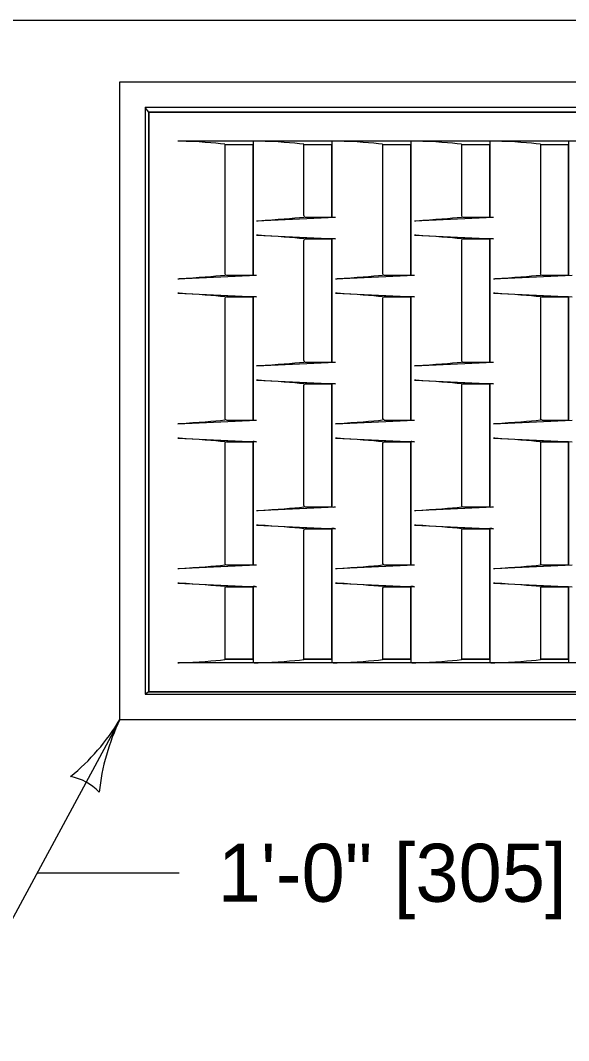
# Model space of a CAD drawing. Extents: x 49991.4 to 50021, y 49987.6 to 50011.4.
# Drawn here: x 50001.882 to 50002.449, y 49997.234 to 49998.29 of the extents above; entities that cross this region are included whole.
import ezdxf

# ---------------------------------------------------------------- set-up
doc = ezdxf.new("R2010")
doc.units = 0
for name, color, linetype in [('Level 1', 7, 'Continuous'), ('Level 18', 7, 'Continuous'), ('Level 2', 7, 'Continuous'), ('Level 3', 7, 'Continuous')]:
    doc.layers.add(name, color=color, linetype=linetype)

msp = doc.modelspace()

# ---------------------------------------------------------------- linework, layer by layer
at = {"layer": 'Level 1'}
for p, q in [((50003.5566, 49998.2898), (50001.1926, 49998.2898)), ((50001.9846, 49997.5662), (50001.9846, 49998.2261)), ((50001.9846, 49998.2261), (50002.7646, 49998.2261)), ((50002.0108, 49998.1998), (50002.0108, 49997.5925)), ((50002.0146, 49998.195), (50002.0108, 49998.1998)), ((50002.7383, 49998.1998), (50002.0108, 49998.1998)), ((50002.7346, 49998.195), (50002.0146, 49998.195)), ((50002.6946, 49998.165), (50002.0446, 49998.165)), ((50002.1224, 49998.1647), (50002.1224, 49998.0262)), ((50002.2039, 49998.1647), (50002.2039, 49998.0862)), ((50002.2855, 49998.1647), (50002.2855, 49998.0262)), ((50002.367, 49998.1647), (50002.367, 49998.0862)), ((50002.4486, 49998.1647), (50002.4486, 49998.0262)), ((50002.0932, 49998.1617), (50002.0932, 49998.0278)), ((50002.1224, 49998.1612), (50002.0932, 49998.1612)), ((50002.1747, 49998.1617), (50002.1747, 49998.1612)), ((50002.2039, 49998.1612), (50002.1747, 49998.1612)), ((50002.1747, 49998.1612), (50002.1747, 49998.0878)), ((50002.2563, 49998.1617), (50002.2563, 49998.1612)), ((50002.2855, 49998.1612), (50002.2563, 49998.1612)), ((50002.2563, 49998.1612), (50002.2563, 49998.0278)), ((50002.3378, 49998.1617), (50002.3378, 49998.1612)), ((50002.367, 49998.1612), (50002.3378, 49998.1612)), ((50002.3378, 49998.1612), (50002.3378, 49998.0878)), ((50002.4194, 49998.1617), (50002.4194, 49998.1612)), ((50002.4486, 49998.1612), (50002.4194, 49998.1612)), ((50002.4194, 49998.1612), (50002.4194, 49998.0278)), ((50002.1261, 49998.0825), (50002.2077, 49998.0862)), ((50002.1763, 49998.0862), (50002.2039, 49998.0862)), ((50002.2892, 49998.0825), (50002.3708, 49998.0862)), ((50002.3394, 49998.0862), (50002.367, 49998.0862)), ((50002.1261, 49998.0675), (50002.2077, 49998.0637)), ((50002.2892, 49998.0675), (50002.3708, 49998.0637)), ((50002.1747, 49998.0622), (50002.1747, 49997.9378)), ((50002.1763, 49998.0637), (50002.2039, 49998.0637)), ((50002.2039, 49998.0638), (50002.2039, 49997.9362)), ((50002.3378, 49998.0622), (50002.3378, 49997.9378)), ((50002.3394, 49998.0637), (50002.367, 49998.0637)), ((50002.367, 49998.0638), (50002.367, 49997.9362)), ((50002.0446, 49998.0225), (50002.1261, 49998.0263)), ((50002.0948, 49998.0263), (50002.1224, 49998.0263)), ((50002.2077, 49998.0225), (50002.2892, 49998.0263)), ((50002.2579, 49998.0263), (50002.2855, 49998.0263)), ((50002.3708, 49998.0225), (50002.4523, 49998.0263)), ((50002.4209, 49998.0263), (50002.4486, 49998.0263)), ((50002.0446, 49998.0075), (50002.1261, 49998.0038)), ((50002.0948, 49998.0038), (50002.1224, 49998.0038)), ((50002.1224, 49998.0038), (50002.1224, 49997.8763)), ((50002.2077, 49998.0075), (50002.2892, 49998.0038)), ((50002.2579, 49998.0038), (50002.2855, 49998.0038)), ((50002.2855, 49998.0038), (50002.2855, 49997.8763)), ((50002.3708, 49998.0075), (50002.4523, 49998.0038)), ((50002.4209, 49998.0038), (50002.4486, 49998.0038)), ((50002.4486, 49998.0038), (50002.4486, 49997.8763)), ((50002.0932, 49998.0022), (50002.0932, 49997.8779)), ((50002.2563, 49998.0022), (50002.2563, 49997.8779)), ((50002.4194, 49998.0022), (50002.4194, 49997.8779)), ((50002.1261, 49997.9325), (50002.2077, 49997.9363)), ((50002.1763, 49997.9363), (50002.2039, 49997.9363)), ((50002.2892, 49997.9325), (50002.3708, 49997.9363)), ((50002.3394, 49997.9363), (50002.367, 49997.9363)), ((50002.1261, 49997.9175), (50002.2077, 49997.9138)), ((50002.1747, 49997.9122), (50002.1747, 49997.7879)), ((50002.1763, 49997.9138), (50002.2039, 49997.9138)), ((50002.2039, 49997.9138), (50002.2039, 49997.7863)), ((50002.2892, 49997.9175), (50002.3708, 49997.9138)), ((50002.3378, 49997.9122), (50002.3378, 49997.7879)), ((50002.3394, 49997.9138), (50002.367, 49997.9138)), ((50002.367, 49997.9138), (50002.367, 49997.7863)), ((50002.0446, 49997.8725), (50002.1261, 49997.8763)), ((50002.0948, 49997.8763), (50002.1224, 49997.8763)), ((50002.2077, 49997.8725), (50002.2892, 49997.8763)), ((50002.2579, 49997.8763), (50002.2855, 49997.8763)), ((50002.3708, 49997.8725), (50002.4523, 49997.8763)), ((50002.4209, 49997.8763), (50002.4486, 49997.8763)), ((50002.0446, 49997.8575), (50002.1261, 49997.8538)), ((50002.2077, 49997.8575), (50002.2892, 49997.8538)), ((50002.3708, 49997.8575), (50002.4523, 49997.8538)), ((50002.0932, 49997.8522), (50002.0932, 49997.7279)), ((50002.0948, 49997.8538), (50002.1224, 49997.8538)), ((50002.1224, 49997.8538), (50002.1224, 49997.7263)), ((50002.2563, 49997.8522), (50002.2563, 49997.7279)), ((50002.2579, 49997.8538), (50002.2855, 49997.8538)), ((50002.2855, 49997.8538), (50002.2855, 49997.7263)), ((50002.4194, 49997.8522), (50002.4194, 49997.7279)), ((50002.4209, 49997.8538), (50002.4486, 49997.8538)), ((50002.4486, 49997.8538), (50002.4486, 49997.7263)), ((50002.1261, 49997.7826), (50002.2077, 49997.7863)), ((50002.1763, 49997.7863), (50002.2039, 49997.7863)), ((50002.2892, 49997.7826), (50002.3708, 49997.7863)), ((50002.3394, 49997.7863), (50002.367, 49997.7863)), ((50002.1261, 49997.7676), (50002.2077, 49997.7638)), ((50002.1747, 49997.7623), (50002.1747, 49997.6289)), ((50002.1763, 49997.7638), (50002.2039, 49997.7638)), ((50002.2039, 49997.7639), (50002.2039, 49997.6254)), ((50002.2892, 49997.7676), (50002.3708, 49997.7638)), ((50002.3378, 49997.7623), (50002.3378, 49997.6289)), ((50002.3394, 49997.7638), (50002.367, 49997.7638)), ((50002.367, 49997.7639), (50002.367, 49997.6254)), ((50002.0446, 49997.7226), (50002.1261, 49997.7263)), ((50002.0948, 49997.7263), (50002.1224, 49997.7263)), ((50002.2077, 49997.7226), (50002.2892, 49997.7263)), ((50002.2579, 49997.7263), (50002.2855, 49997.7263)), ((50002.3708, 49997.7226), (50002.4523, 49997.7263)), ((50002.4209, 49997.7263), (50002.4486, 49997.7263)), ((50002.0446, 49997.7076), (50002.1261, 49997.7038)), ((50002.0932, 49997.7023), (50002.0932, 49997.6284)), ((50002.0948, 49997.7038), (50002.1224, 49997.7038)), ((50002.1224, 49997.7039), (50002.1224, 49997.6254)), ((50002.2077, 49997.7076), (50002.2892, 49997.7038)), ((50002.2563, 49997.7023), (50002.2563, 49997.6289)), ((50002.2579, 49997.7038), (50002.2855, 49997.7038)), ((50002.2855, 49997.7039), (50002.2855, 49997.6254)), ((50002.3708, 49997.7076), (50002.4523, 49997.7038)), ((50002.4194, 49997.7023), (50002.4194, 49997.6289)), ((50002.4209, 49997.7038), (50002.4486, 49997.7038)), ((50002.4486, 49997.7039), (50002.4486, 49997.6254)), ((50002.6946, 49997.6251), (50002.0446, 49997.6251)), ((50002.1224, 49997.6289), (50002.0932, 49997.6289)), ((50002.2039, 49997.6289), (50002.1747, 49997.6289)), ((50002.1747, 49997.6289), (50002.1747, 49997.6284)), ((50002.2855, 49997.6289), (50002.2563, 49997.6289)), ((50002.2563, 49997.6289), (50002.2563, 49997.6284)), ((50002.367, 49997.6289), (50002.3378, 49997.6289)), ((50002.3378, 49997.6289), (50002.3378, 49997.6284)), ((50002.4486, 49997.6289), (50002.4194, 49997.6289)), ((50002.4194, 49997.6289), (50002.4194, 49997.6284)), ((50002.0146, 49997.5951), (50002.0108, 49997.5925)), ((50002.0108, 49997.5925), (50002.7383, 49997.5925)), ((50002.0146, 49997.5951), (50002.7346, 49997.5951)), ((50002.7646, 49997.5662), (50001.9846, 49997.5662))]:
    msp.add_line(p, q, dxfattribs=at)
msp.add_lwpolyline([(50002.0146, 49998.195), (50002.7344, 49998.195), (50002.7344, 49997.5951), (50002.0146, 49997.5951)], close=True, dxfattribs=at)
for points in [[(50002.0932, 49998.1612), (50002.0932, 49998.0278)], [(50002.0948, 49998.0263), (50002.1224, 49998.0263), (50002.1224, 49998.1612), (50002.0932, 49998.1612)], [(50002.2039, 49998.0862), (50002.2039, 49998.1612), (50002.1747, 49998.1612), (50002.1747, 49998.0878)], [(50002.2855, 49998.0263), (50002.2855, 49998.1612), (50002.2563, 49998.1612), (50002.2563, 49998.0278)], [(50002.367, 49998.0862), (50002.367, 49998.1612), (50002.3378, 49998.1612), (50002.3378, 49998.0878)], [(50002.4486, 49998.0263), (50002.4486, 49998.1612), (50002.4194, 49998.1612), (50002.4194, 49998.0278)], [(50002.1763, 49998.0862), (50002.2039, 49998.0862)], [(50002.3394, 49998.0862), (50002.367, 49998.0862)], [(50002.1747, 49998.0622), (50002.1747, 49997.9378)], [(50002.2039, 49997.9363), (50002.2039, 49998.0637), (50002.1763, 49998.0637)], [(50002.2579, 49998.0263), (50002.2855, 49998.0263)], [(50002.4209, 49998.0263), (50002.4486, 49998.0263)], [(50002.1224, 49997.8763), (50002.1224, 49998.0038), (50002.0948, 49998.0038)], [(50002.2855, 49997.8763), (50002.2855, 49998.0038), (50002.2579, 49998.0038)], [(50002.4486, 49997.8763), (50002.4486, 49998.0038), (50002.4209, 49998.0038)], [(50002.0932, 49998.0022), (50002.0932, 49997.8779)], [(50002.2563, 49998.0022), (50002.2563, 49997.8779)], [(50002.4194, 49998.0022), (50002.4194, 49997.8779)], [(50002.1763, 49997.9363), (50002.2039, 49997.9363)], [(50002.1747, 49997.9122), (50002.1747, 49997.7879)], [(50002.2039, 49997.7863), (50002.2039, 49997.9138), (50002.1763, 49997.9138)], [(50002.0948, 49997.8763), (50002.1224, 49997.8763)], [(50002.2579, 49997.8763), (50002.2855, 49997.8763)], [(50002.4209, 49997.8763), (50002.4486, 49997.8763)], [(50002.0932, 49997.8522), (50002.0932, 49997.7279)], [(50002.1224, 49997.7263), (50002.1224, 49997.8538), (50002.0948, 49997.8538)], [(50002.2563, 49997.8522), (50002.2563, 49997.7279)], [(50002.2855, 49997.7263), (50002.2855, 49997.8538), (50002.2579, 49997.8538)], [(50002.1763, 49997.7863), (50002.2039, 49997.7863)], [(50002.1747, 49997.7623), (50002.1747, 49997.6289), (50002.2039, 49997.6289)], [(50002.2039, 49997.6289), (50002.2039, 49997.7638), (50002.1763, 49997.7638)], [(50002.3378, 49997.7623), (50002.3378, 49997.6289), (50002.367, 49997.6289)], [(50002.367, 49997.6289), (50002.367, 49997.7638), (50002.3394, 49997.7638)], [(50002.0948, 49997.7263), (50002.1224, 49997.7263)], [(50002.2579, 49997.7263), (50002.2855, 49997.7263)], [(50002.2563, 49997.7023), (50002.2563, 49997.6289), (50002.2855, 49997.6289)], [(50002.2855, 49997.6289), (50002.2855, 49997.7038), (50002.2579, 49997.7038)]]:
    msp.add_lwpolyline(points, dxfattribs=at)
for centre, radius, start, end in [((50002.3746, 49998.2898), 1.2045, 180, 0), ((50002.3746, 49998.2898), 1.182, 180, 0), ((50002.1763, 49998.0878), 0.00156, 180, 270), ((50002.1763, 49998.0878), 0.00156, 180, 270), ((50002.3394, 49998.0878), 0.00156, 180, 270), ((50002.3394, 49998.0878), 0.00156, 180, 270), ((50002.1763, 49998.0622), 0.00156, 90, 180), ((50002.1763, 49998.0622), 0.00156, 90, 180), ((50002.3394, 49998.0622), 0.00156, 90, 180), ((50002.0948, 49998.0278), 0.00156, 180, 270), ((50002.0948, 49998.0278), 0.00156, 180, 270), ((50002.2579, 49998.0278), 0.00156, 180, 270), ((50002.2579, 49998.0278), 0.00156, 180, 270), ((50002.4209, 49998.0278), 0.00156, 180, 270), ((50002.4209, 49998.0278), 0.00156, 180, 270), ((50002.0948, 49998.0022), 0.00156, 90, 180), ((50002.0948, 49998.0022), 0.00156, 90, 180), ((50002.2579, 49998.0022), 0.00156, 90, 180), ((50002.2579, 49998.0022), 0.00156, 90, 180), ((50002.4209, 49998.0022), 0.00156, 90, 180), ((50002.4209, 49998.0022), 0.00156, 90, 180), ((50002.1763, 49997.9378), 0.00156, 180, 270), ((50002.1763, 49997.9378), 0.00156, 180, 270), ((50002.3394, 49997.9378), 0.00156, 180, 270), ((50002.1763, 49997.9122), 0.00156, 90, 180), ((50002.1763, 49997.9122), 0.00156, 90, 180), ((50002.3394, 49997.9122), 0.00156, 90, 180), ((50002.0948, 49997.8779), 0.00156, 180, 270), ((50002.0948, 49997.8779), 0.00156, 180, 270), ((50002.2579, 49997.8779), 0.00156, 180, 270), ((50002.2579, 49997.8779), 0.00156, 180, 270), ((50002.4209, 49997.8779), 0.00156, 180, 270), ((50002.4209, 49997.8779), 0.00156, 180, 270), ((50002.0948, 49997.8522), 0.00156, 90, 180), ((50002.0948, 49997.8522), 0.00156, 90, 180), ((50002.2579, 49997.8522), 0.00156, 90, 180), ((50002.2579, 49997.8522), 0.00156, 90, 180), ((50002.4209, 49997.8522), 0.00156, 90, 180), ((50002.1763, 49997.7879), 0.00156, 180, 270), ((50002.1763, 49997.7879), 0.00156, 180, 270), ((50002.3394, 49997.7879), 0.00156, 180, 270), ((50002.1763, 49997.7623), 0.00156, 90, 180), ((50002.1763, 49997.7623), 0.00156, 90, 180), ((50002.3394, 49997.7623), 0.00156, 90, 180), ((50002.3394, 49997.7623), 0.00156, 90, 180), ((50002.0948, 49997.7279), 0.00156, 180, 270), ((50002.0948, 49997.7279), 0.00156, 180, 270), ((50002.2579, 49997.7279), 0.00156, 180, 270), ((50002.2579, 49997.7279), 0.00156, 180, 270), ((50002.4209, 49997.7279), 0.00156, 180, 270), ((50002.0948, 49997.7023), 0.00156, 90, 180), ((50002.2579, 49997.7023), 0.00156, 90, 180), ((50002.2579, 49997.7023), 0.00156, 90, 180), ((50002.4209, 49997.7023), 0.00156, 90, 180)]:
    msp.add_arc(centre, radius, start, end, dxfattribs=at)
for centre, major_axis, ratio, start_param, end_param in [((50002.0025, 49998.1576), (0.105, 0), 0.076923, 0.527586, 1.142), ((50002.1261, 49998.1647), (0.00375, 0), 0.076923, 1.570796, 3.141593), ((50002.1261, 49998.1647), (0.00375, 0), 0.076923, 1.142, 1.570796), ((50002.084, 49998.1576), (0.105, 0), 0.076923, 0.527586, 1.142), ((50002.2077, 49998.1647), (0.00375, 0), 0.076923, 1.570796, 3.141593), ((50002.2077, 49998.1647), (0.00375, 0), 0.076923, 1.142, 1.570796), ((50002.1656, 49998.1576), (0.105, 0), 0.076923, 0.527586, 1.142), ((50002.2892, 49998.1647), (0.00375, 0), 0.076923, 1.570796, 3.141593), ((50002.2892, 49998.1647), (0.00375, 0), 0.076923, 1.142, 1.570796), ((50002.2471, 49998.1576), (0.105, 0), 0.076923, 0.527586, 1.142), ((50002.3708, 49998.1647), (0.00375, 0), 0.076923, 1.570796, 3.141593), ((50002.3708, 49998.1647), (0.00375, 0), 0.076923, 1.142, 1.570796), ((50002.3287, 49998.1576), (0.105, 0), 0.076923, 0.527586, 1.142), ((50002.084, 49998.084), (-0.105, -0.0048), 0.035758, 1.997966, 2.612379), ((50002.2077, 49998.0864), (-0.00375, -0.00017), 0.035758, 6.281558, 7.852354), ((50002.2892, 49998.0826), (-0.00375, -0.00017), 0.035758, 1.569169, 1.997966), ((50002.2471, 49998.084), (-0.105, -0.0048), 0.035758, 1.997966, 2.612379), ((50002.3708, 49998.0864), (-0.00375, -0.00017), 0.035758, 6.281558, 7.852354), ((50002.084, 49998.066), (0.105, -0.0048), 0.035758, 0.529214, 1.143627), ((50002.2892, 49998.0674), (0.00375, -0.00017), 0.035758, 1.143627, 1.572424), ((50002.2471, 49998.066), (0.105, -0.0048), 0.035758, 0.529214, 1.143627), ((50002.2077, 49998.0636), (0.00375, -0.00017), 0.035758, 1.572424, 3.14322), ((50002.3708, 49998.0636), (0.00375, -0.00017), 0.035758, 1.572424, 3.14322), ((50002.0025, 49998.024), (-0.105, -0.0048), 0.035758, 1.997966, 2.612379), ((50002.1261, 49998.0264), (-0.00375, -0.00017), 0.035758, 6.281558, 7.852354), ((50002.1656, 49998.024), (-0.105, -0.0048), 0.035758, 1.997966, 2.612379), ((50002.2892, 49998.0264), (-0.00375, -0.00017), 0.035758, 6.281558, 7.852354), ((50002.3287, 49998.024), (-0.105, -0.0048), 0.035758, 1.997966, 2.612379), ((50002.0446, 49998.0226), (-0.00375, -0.00017), 0.035758, 1.569169, 1.997966), ((50002.0446, 49998.0074), (0.00375, -0.00017), 0.035758, 1.143627, 1.572424), ((50002.0025, 49998.006), (0.105, -0.0048), 0.035758, 0.529214, 1.143627), ((50002.1261, 49998.0036), (0.00375, -0.00017), 0.035758, 1.572424, 3.14322), ((50002.1656, 49998.006), (0.105, -0.0048), 0.035758, 0.529214, 1.143627), ((50002.2892, 49998.0036), (0.00375, -0.00017), 0.035758, 1.572424, 3.14322), ((50002.3287, 49998.006), (0.105, -0.0048), 0.035758, 0.529214, 1.143627), ((50002.084, 49997.934), (-0.105, -0.0048), 0.035758, 1.997966, 2.612379), ((50002.2077, 49997.9364), (-0.00375, -0.00017), 0.035758, 6.281558, 7.852354), ((50002.2892, 49997.9327), (-0.00375, -0.00017), 0.035758, 1.569169, 1.997966), ((50002.2471, 49997.934), (-0.105, -0.0048), 0.035758, 1.997966, 2.612379), ((50002.3708, 49997.9364), (-0.00375, -0.00017), 0.035758, 6.281558, 7.852354), ((50002.084, 49997.916), (0.105, -0.0048), 0.035758, 0.529214, 1.143627), ((50002.2077, 49997.9136), (0.00375, -0.00017), 0.035758, 1.572424, 3.14322), ((50002.2892, 49997.9174), (0.00375, -0.00017), 0.035758, 1.143627, 1.572424), ((50002.2471, 49997.916), (0.105, -0.0048), 0.035758, 0.529214, 1.143627), ((50002.3708, 49997.9136), (0.00375, -0.00017), 0.035758, 1.572424, 3.14322), ((50002.0025, 49997.8741), (-0.105, -0.0048), 0.035758, 1.997966, 2.612379), ((50002.1261, 49997.8764), (-0.00375, -0.00017), 0.035758, 6.281558, 7.852354), ((50002.1656, 49997.8741), (-0.105, -0.0048), 0.035758, 1.997966, 2.612379), ((50002.2892, 49997.8764), (-0.00375, -0.00017), 0.035758, 6.281558, 7.852354), ((50002.3287, 49997.8741), (-0.105, -0.0048), 0.035758, 1.997966, 2.612379), ((50002.0025, 49997.856), (0.105, -0.0048), 0.035758, 0.529214, 1.143627), ((50002.1656, 49997.856), (0.105, -0.0048), 0.035758, 0.529214, 1.143627), ((50002.3287, 49997.856), (0.105, -0.0048), 0.035758, 0.529214, 1.143627), ((50002.1261, 49997.8537), (0.00375, -0.00017), 0.035758, 1.572424, 3.14322), ((50002.2892, 49997.8537), (0.00375, -0.00017), 0.035758, 1.572424, 3.14322), ((50002.084, 49997.7841), (-0.105, -0.0048), 0.035758, 1.997966, 2.612379), ((50002.2077, 49997.7865), (-0.00375, -0.00017), 0.035758, 6.281558, 7.852354), ((50002.2892, 49997.7827), (-0.00375, -0.00017), 0.035758, 1.569169, 1.997966), ((50002.2471, 49997.7841), (-0.105, -0.0048), 0.035758, 1.997966, 2.612379), ((50002.3708, 49997.7865), (-0.00375, -0.00017), 0.035758, 6.281558, 7.852354), ((50002.084, 49997.7661), (0.105, -0.0048), 0.035758, 0.529214, 1.143627), ((50002.2077, 49997.7637), (0.00375, -0.00017), 0.035758, 1.572424, 3.14322), ((50002.2892, 49997.7674), (0.00375, -0.00017), 0.035758, 1.143627, 1.572424), ((50002.2471, 49997.7661), (0.105, -0.0048), 0.035758, 0.529214, 1.143627), ((50002.3708, 49997.7637), (0.00375, -0.00017), 0.035758, 1.572424, 3.14322), ((50002.0025, 49997.7241), (-0.105, -0.0048), 0.035758, 1.997966, 2.612379), ((50002.1261, 49997.7265), (-0.00375, -0.00017), 0.035758, 6.281558, 7.852354), ((50002.1656, 49997.7241), (-0.105, -0.0048), 0.035758, 1.997966, 2.612379), ((50002.2892, 49997.7265), (-0.00375, -0.00017), 0.035758, 6.281558, 7.852354), ((50002.3287, 49997.7241), (-0.105, -0.0048), 0.035758, 1.997966, 2.612379), ((50002.0025, 49997.7061), (0.105, -0.0048), 0.035758, 0.529214, 1.143627), ((50002.1261, 49997.7037), (0.00375, -0.00017), 0.035758, 1.572424, 3.14322), ((50002.1656, 49997.7061), (0.105, -0.0048), 0.035758, 0.529214, 1.143627), ((50002.2892, 49997.7037), (0.00375, -0.00017), 0.035758, 1.572424, 3.14322), ((50002.3287, 49997.7061), (0.105, -0.0048), 0.035758, 0.529214, 1.143627), ((50002.0025, 49997.6325), (0.105, 0), 0.076923, 5.141186, 5.755599), ((50002.1261, 49997.6254), (0.00375, 0), 0.076923, 3.141593, 4.712389), ((50002.1261, 49997.6254), (0.00375, 0), 0.076923, 4.712389, 5.141186), ((50002.084, 49997.6325), (0.105, 0), 0.076923, 5.141186, 5.755599), ((50002.2077, 49997.6254), (0.00375, 0), 0.076923, 3.141593, 4.712389), ((50002.2077, 49997.6254), (0.00375, 0), 0.076923, 4.712389, 5.141186), ((50002.1656, 49997.6325), (0.105, 0), 0.076923, 5.141186, 5.755599), ((50002.2892, 49997.6254), (0.00375, 0), 0.076923, 3.141593, 4.712389), ((50002.2892, 49997.6254), (0.00375, 0), 0.076923, 4.712389, 5.141186), ((50002.2471, 49997.6325), (0.105, 0), 0.076923, 5.141186, 5.755599), ((50002.3708, 49997.6254), (0.00375, 0), 0.076923, 3.141593, 4.712389), ((50002.3708, 49997.6254), (0.00375, 0), 0.076923, 4.712389, 5.141186), ((50002.3287, 49997.6325), (0.105, 0), 0.076923, 5.141186, 5.755599)]:
    msp.add_ellipse(centre, major_axis=major_axis, ratio=ratio, start_param=start_param, end_param=end_param, dxfattribs=at)
at = {"layer": 'Level 18'}
for p, q in [((50002.0146, 49998.195), (50002.0146, 49997.5951)), ((50001.9846, 49997.5662), (50001.9846, 49997.5662))]:
    msp.add_line(p, q, dxfattribs=at)
for points in [[(50002.3378, 49998.0622), (50002.3378, 49997.9378)], [(50002.367, 49997.9363), (50002.367, 49998.0637), (50002.3394, 49998.0637)], [(50002.3394, 49997.9363), (50002.367, 49997.9363)], [(50002.3378, 49997.9122), (50002.3378, 49997.7879)], [(50002.367, 49997.7863), (50002.367, 49997.9138), (50002.3394, 49997.9138)], [(50002.4194, 49997.8522), (50002.4194, 49997.7279)], [(50002.4486, 49997.7263), (50002.4486, 49997.8538), (50002.4209, 49997.8538)], [(50002.3394, 49997.7863), (50002.367, 49997.7863)], [(50002.4209, 49997.7263), (50002.4486, 49997.7263)], [(50002.0932, 49997.7023), (50002.0932, 49997.6289), (50002.1224, 49997.6289)], [(50002.1224, 49997.6289), (50002.1224, 49997.7038), (50002.0948, 49997.7038)], [(50002.4194, 49997.7023), (50002.4194, 49997.6289), (50002.4486, 49997.6289)], [(50002.4486, 49997.6289), (50002.4486, 49997.7038), (50002.4209, 49997.7038)]]:
    msp.add_lwpolyline(points, dxfattribs=at)
for centre, start, end in [((50002.3394, 49998.0622), 90, 180), ((50002.3394, 49997.9378), 180, 270), ((50002.3394, 49997.9122), 90, 180), ((50002.4209, 49997.8522), 90, 180), ((50002.3394, 49997.7879), 180, 270), ((50002.4209, 49997.7279), 180, 270), ((50002.0948, 49997.7023), 90, 180), ((50002.4209, 49997.7023), 90, 180)]:
    msp.add_arc(centre, 0.00156, start, end, dxfattribs=at)
for centre, major_axis, ratio, start_param, end_param in [((50002.0446, 49998.1647), (0.00375, 0), 0.076923, 1.142, 1.570796), ((50002.1261, 49998.0826), (-0.00375, -0.00017), 0.035758, 1.569169, 1.997966), ((50002.1261, 49998.0674), (0.00375, -0.00017), 0.035758, 1.143627, 1.572424), ((50002.2077, 49998.0226), (-0.00375, -0.00017), 0.035758, 1.569169, 1.997966), ((50002.3708, 49998.0226), (-0.00375, -0.00017), 0.035758, 1.569169, 1.997966), ((50002.2077, 49998.0074), (0.00375, -0.00017), 0.035758, 1.143627, 1.572424), ((50002.3708, 49998.0074), (0.00375, -0.00017), 0.035758, 1.143627, 1.572424), ((50002.1261, 49997.9327), (-0.00375, -0.00017), 0.035758, 1.569169, 1.997966), ((50002.1261, 49997.9174), (0.00375, -0.00017), 0.035758, 1.143627, 1.572424), ((50002.0446, 49997.8727), (-0.00375, -0.00017), 0.035758, 1.569169, 1.997966), ((50002.2077, 49997.8727), (-0.00375, -0.00017), 0.035758, 1.569169, 1.997966), ((50002.3708, 49997.8727), (-0.00375, -0.00017), 0.035758, 1.569169, 1.997966), ((50002.0446, 49997.8574), (0.00375, -0.00017), 0.035758, 1.143627, 1.572424), ((50002.2077, 49997.8574), (0.00375, -0.00017), 0.035758, 1.143627, 1.572424), ((50002.3708, 49997.8574), (0.00375, -0.00017), 0.035758, 1.143627, 1.572424), ((50002.1261, 49997.7827), (-0.00375, -0.00017), 0.035758, 1.569169, 1.997966), ((50002.1261, 49997.7674), (0.00375, -0.00017), 0.035758, 1.143627, 1.572424), ((50002.0446, 49997.7227), (-0.00375, -0.00017), 0.035758, 1.569169, 1.997966), ((50002.2077, 49997.7227), (-0.00375, -0.00017), 0.035758, 1.569169, 1.997966), ((50002.3708, 49997.7227), (-0.00375, -0.00017), 0.035758, 1.569169, 1.997966), ((50002.0446, 49997.7075), (0.00375, -0.00017), 0.035758, 1.143627, 1.572424), ((50002.2077, 49997.7075), (0.00375, -0.00017), 0.035758, 1.143627, 1.572424), ((50002.3708, 49997.7075), (0.00375, -0.00017), 0.035758, 1.143627, 1.572424), ((50002.0446, 49997.6254), (0.00375, 0), 0.076923, 4.712389, 5.141186)]:
    msp.add_ellipse(centre, major_axis=major_axis, ratio=ratio, start_param=start_param, end_param=end_param, dxfattribs=at)
at = {"layer": 'Level 3'}
for p, q in [((50001.9846, 49997.5662), (50001.8138, 49997.2493)), ((50001.8992, 49997.4078), (50002.0459, 49997.4078))]:
    msp.add_line(p, q, dxfattribs=at)
for centre, radius, start, end in [((50001.7934, 49997.6797), 0.2223, 309.1323, 329.3158), ((50002.1949, 49997.4659), 0.233, 154.5036, 173.7534), ((50001.9238, 49997.4534), 0.0548, 43.8151, 79.5374)]:
    msp.add_arc(centre, radius, start, end, dxfattribs=at)

# ---------------------------------------------------------------- texts
at = {"layer": 'Level 2'}
msp.add_text('1\'-0" [305]', height=0.06, dxfattribs=at).set_placement((50002.0859, 49997.3778))

doc.saveas('drawing.dxf')
